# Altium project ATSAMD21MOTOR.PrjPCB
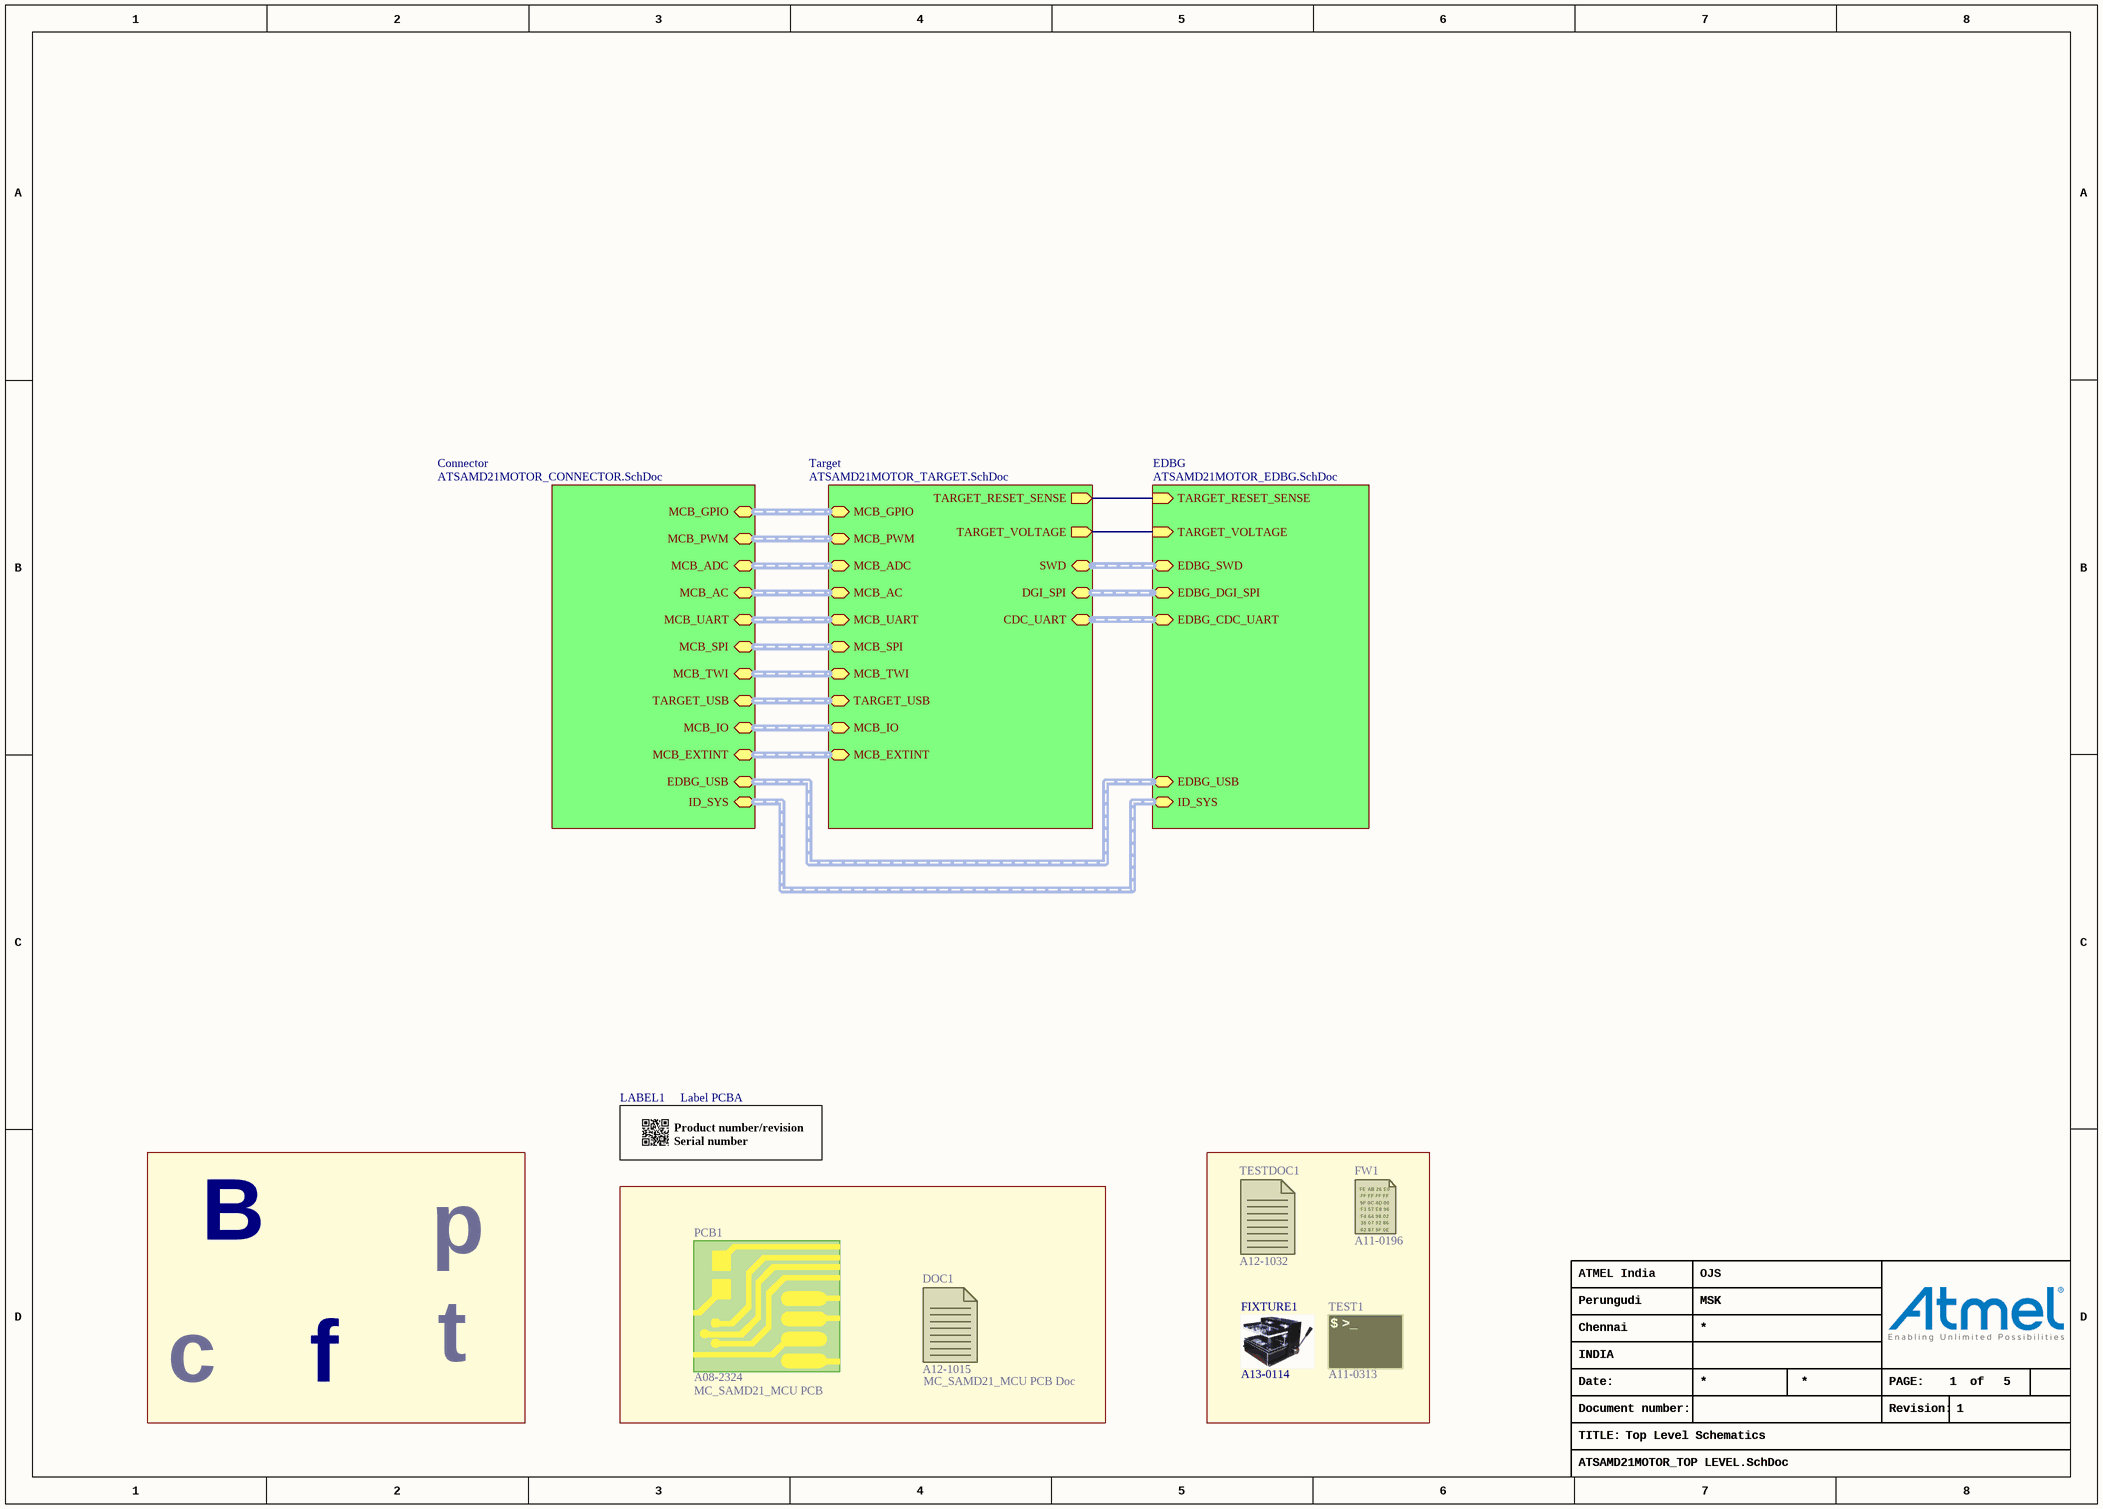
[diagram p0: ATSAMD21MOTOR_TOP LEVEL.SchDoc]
4 sheets, 98 parts. Net scope: hierarchical (ports join the sheet entries above them; power ports are global).
Board file: ATSAMD21MOTOR.PcbDoc
Sheets:
  ATSAMD21MOTOR_TOP LEVEL.SchDoc
    Connector = ATSAMD21MOTOR_CONNECTOR.SchDoc
    EDBG = ATSAMD21MOTOR_EDBG.SchDoc
    Target = ATSAMD21MOTOR_TARGET.SchDoc

## Sheet ATSAMD21MOTOR_TOP LEVEL.SchDoc: Top Level Schematics
size A3; Organization: ATMEL India; Address1: Perungudi; Address2: Chennai; Address3: INDIA; Revision: 1; SheetNumber: 1; SheetTotal: 5; CheckedBy: MSK; DrawnBy: OJS; Engineer: OJS; PageSetup: Record=PageOptions¦CenterHorizontal=True¦CenterVertical=True¦PrintScale=1.01¦XCorrection=1.00¦YCorrection=1.00¦PrintKind=1¦BorderSize=5000000¦LeftOffset=0¦BottomOffset=0¦Orientation=2¦PaperLength=1000¦PaperWidth=1000¦Scale=100¦PaperSource=7¦PrintQuality=-4¦MediaType=1¦DitherType=10¦PaperKind=Letter¦PrintScaleMode=1

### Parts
DOC1  value MC_SAMD21_MCU PCB Doc  AN: A12-1015  (hidden comment: DOCUMENTATION)  (mechanical)
FIXTURE1  AN: A13-0114  (hidden comment: JIG)  (mechanical)
FW1  AN: A11-0196  (hidden comment: FW)  (mechanical)
LABEL1  value Label PCBA  [AP8-00317]  (hidden comment: PCBA_LABEL)
PCB1  value MC_SAMD21_MCU PCB  AN: A08-2324  (hidden comment: PCB)  (mechanical)
TEST1  AN: A11-0313  (hidden comment: TEST)  (mechanical)
TESTDOC1  AN: A12-1032  (hidden comment: TESTDOC)  (mechanical)

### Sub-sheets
Connector = ATSAMD21MOTOR_CONNECTOR.SchDoc: MCB_GPIO (harness MCB_GPIO), MCB_PWM (harness MCB_PWM), MCB_ADC (harness MCB_ADC), MCB_AC (harness MCB_AC), MCB_SPI (harness MCB_SPI), MCB_UART (harness MCB_UART), MCB_TWI (harness MCB_TWI), ID_SYS (harness ID_SYS), EDBG_USB (harness EDBG_USB), TARGET_USB (harness TARGET_USB), MCB_IO (harness MCB_IO), MCB_EXTINT (harness MCB_EXTINT)
EDBG = ATSAMD21MOTOR_EDBG.SchDoc: EDBG_CDC_UART (harness CDC_UART), EDBG_DGI_SPI (harness DGI_SPI), ID_SYS (harness ID_SYS), TARGET_RESET_SENSE (in), EDBG_SWD (harness SWD), EDBG_USB (harness EDBG_USB), TARGET_VOLTAGE (in)
Target = ATSAMD21MOTOR_TARGET.SchDoc: SWD (harness SWD), DGI_SPI (harness DGI_SPI), TARGET_RESET_SENSE (out), MCB_GPIO (harness MCB_GPIO), MCB_PWM (harness MCB_PWM), MCB_ADC (harness MCB_ADC), MCB_AC (harness MCB_AC), MCB_SPI (harness MCB_SPI), MCB_UART (harness MCB_UART), MCB_TWI (harness MCB_TWI), CDC_UART (harness CDC_UART), TARGET_USB (harness TARGET_USB), TARGET_VOLTAGE (out), MCB_IO (harness MCB_IO), MCB_EXTINT (harness MCB_EXTINT)

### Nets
EDBG_ADC0: sheet EDBG/TARGET_VOLTAGE, sheet Target/TARGET_VOLTAGE
TARGET_RESET_SENSE: sheet EDBG/TARGET_RESET_SENSE, sheet Target/TARGET_RESET_SENSE

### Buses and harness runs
harness sheet Connector/EDBG_USB = sheet EDBG/EDBG_USB
harness sheet Connector/ID_SYS = sheet EDBG/ID_SYS
harness sheet Connector/MCB_AC = sheet Target/MCB_AC
harness sheet Connector/MCB_ADC = sheet Target/MCB_ADC
harness sheet Connector/MCB_EXTINT = sheet Target/MCB_EXTINT
harness sheet Connector/MCB_GPIO = sheet Target/MCB_GPIO
harness sheet Connector/MCB_IO = sheet Target/MCB_IO
harness sheet Connector/MCB_PWM = sheet Target/MCB_PWM
harness sheet Connector/MCB_SPI = sheet Target/MCB_SPI
harness sheet Connector/MCB_TWI = sheet Target/MCB_TWI
harness sheet Connector/MCB_UART = sheet Target/MCB_UART
harness sheet Connector/TARGET_USB = sheet Target/TARGET_USB
harness sheet EDBG/EDBG_CDC_UART = sheet Target/CDC_UART
harness sheet EDBG/EDBG_DGI_SPI = sheet Target/DGI_SPI
harness sheet EDBG/EDBG_SWD = sheet Target/SWD

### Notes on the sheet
- B
- p
- c
- f
- t
- Date:
- PAGE:
- of
- TITLE:
- Document number:
- Revision:

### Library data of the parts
DOC1 = A12-1015: MC_SAMD21_MCU PCB Documentation; PartGroup: Documentation,PCBA Documents,Atmel
FIXTURE1 = A13-0114: Test Fixture for BLDC Motor driver; PartGroup: Test Equipment,Test Fixtures
FW1 = A11-0196: EDBG secured firmware; PartGroup: Software,Firmware,Tools
LABEL1 = A09-0611: PCBA identification label PP Top White Gloss; PartGroup: Mechanical devices,Packaging materials,Printed Labels; Manufacturer: ACT Logimark AS; MPN: 505462
PCB1 = A08-2324: MC_SAMD21_MCU PCB gerber; PartGroup: Mechanical devices,Printed circuit boards
TEST1 = A11-0313: ATSAMD21BLDC24V-STK test software; PartGroup: Software,Test software,Starter Kit
TESTDOC1 = A12-1032: ATSAMD21BLDC24V-STK test instruction; PartGroup: Documentation,Procedures,Test Instructions

## Sheet ATSAMD21MOTOR_CONNECTOR.SchDoc: Daughter Board Connector
size A3; Organization: ATMEL India; Address1: Perungudi; Address2: Chennai; Address3: INDIA; Revision: 1; SheetNumber: 3; SheetTotal: 5; CheckedBy: MSK; DrawnBy: OJS; PageSetup: Record=PageOptions¦CenterHorizontal=True¦CenterVertical=True¦PrintScale=1.01¦XCorrection=1.00¦YCorrection=1.00¦PrintKind=1¦BorderSize=5000000¦LeftOffset=0¦BottomOffset=0¦Orientation=2¦PaperLength=1000¦PaperWidth=1000¦Scale=100¦PaperSource=7¦PrintQuality=-4¦MediaType=1¦DitherType=10¦PaperKind=A3 (297 x 420 mm)¦PrintScaleMode=1
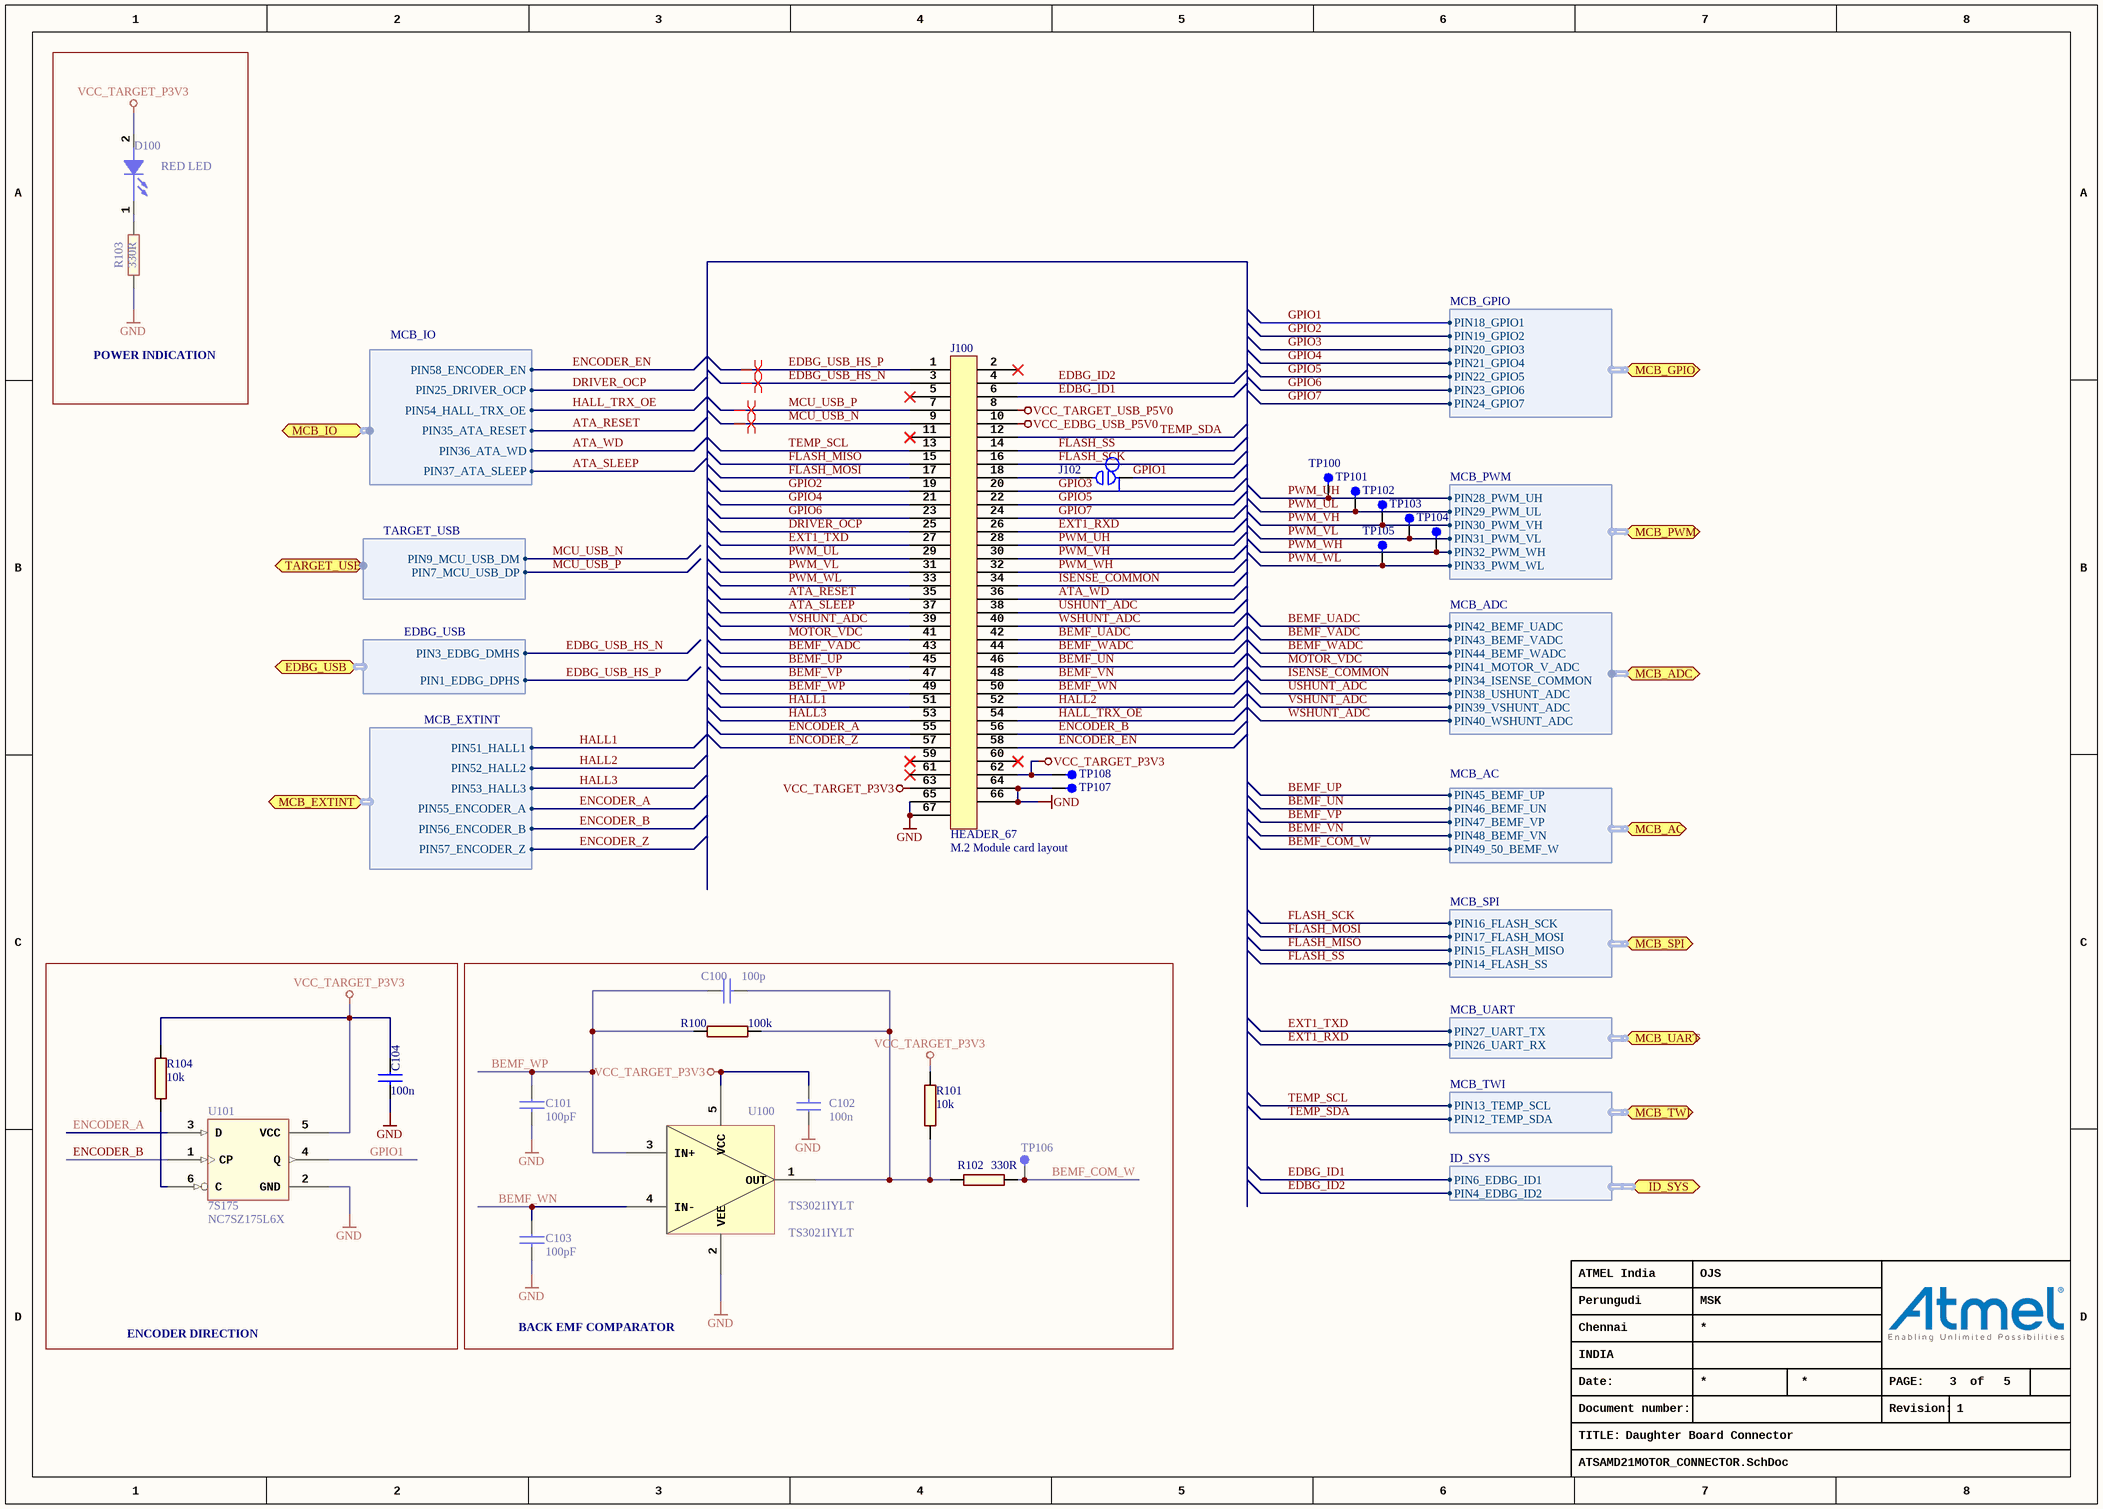
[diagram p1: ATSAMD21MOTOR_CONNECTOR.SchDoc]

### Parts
C100  value 100p  [AP1-00002]  (hidden comment: #Farnell reference  722110RL)
C101  value 100pF  [AP1-00002]  (hidden comment: MPN back-ported from Escatec 29-09-2009)
C102  value 100n  [AP1-00002]  (hidden comment: CAP-NONPOL)
C103  value 100pF  [AP1-00002]  (hidden comment: MPN back-ported from Escatec 29-09-2009)
C104  value 100n  [AP1-00001]  (hidden comment: CAP-NONPOL)
D100  LED_12  [AP4-00013]  (value not drawn)
J100  HEADER_67  value M.2 Module card layout  [AP9-00138]
J102  SMD-STRAP_OPEN  [AP9-00034]  (value not drawn)  (net tie, no BOM)
R100  value 100k  [AP2-00001]  (hidden comment: R2)
R101  value 10k  [AP2-00000]  (hidden comment: R2)
R102  value 330R  [AP2-00001]  (hidden comment: R2)
R103  value 330R  [AP2-00000]  (hidden comment: R2)
R104  value 10k  [AP2-00000]  (hidden comment: R2)
TP100  TESTPOINT  [AP8-00010]  (value not drawn)  (no BOM)
TP101  TESTPOINT  [AP8-00010]  (value not drawn)  (no BOM)
TP102  TESTPOINT  [AP8-00010]  (value not drawn)  (no BOM)
TP103  TESTPOINT  [AP8-00010]  (value not drawn)  (no BOM)
TP104  TESTPOINT  [AP8-00010]  (value not drawn)  (no BOM)
TP105  TESTPOINT  [AP8-00010]  (value not drawn)  (no BOM)
TP106  TESTPOINT  [AP8-00010]  (value not drawn)  (no BOM)
TP107  TESTPOINT  [AP8-00010]  (value not drawn)  (no BOM)
TP108  TESTPOINT  [AP8-00010]  (value not drawn)  (no BOM)
U100  TS3021IYLT  [AP6-00014]
U101  7S175  value NC7SZ175L6X  [AP6-00076]

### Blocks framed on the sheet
ENCODER DIRECTION: C104 R104 U101
BACK EMF COMPARATOR: C100-C103 R100-R102 TP106 U100

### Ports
EDBG_USB (harness EDBG_USB), ID_SYS (harness ID_SYS), MCB_AC (harness MCB_AC), MCB_ADC (harness MCB_ADC), MCB_EXTINT (harness MCB_EXTINT), MCB_GPIO (harness MCB_GPIO), MCB_IO (harness MCB_IO), MCB_PWM (harness MCB_PWM), MCB_SPI (harness MCB_SPI), MCB_TWI (harness MCB_TWI), MCB_UART (harness MCB_UART), TARGET_USB (harness TARGET_USB)

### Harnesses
ID_SYS: PIN4_EDBG_ID2, PIN6_EDBG_ID1
EDBG_USB: PIN3_EDBG_DMHS, PIN1_EDBG_DPHS
MCB_EXTINT: PIN51_HALL1, PIN52_HALL2, PIN53_HALL3, PIN55_ENCODER_A, PIN56_ENCODER_B, PIN57_ENCODER_Z
MCB_GPIO: PIN18_GPIO1, PIN19_GPIO2, PIN20_GPIO3, PIN21_GPIO4, PIN22_GPIO5, PIN23_GPIO6, PIN24_GPIO7
MCB_PWM: PIN28_PWM_UH, PIN29_PWM_UL, PIN30_PWM_VH, PIN31_PWM_VL, PIN32_PWM_WH, PIN33_PWM_WL
MCB_AC: PIN45_BEMF_UP, PIN46_BEMF_UN, PIN47_BEMF_VP, PIN48_BEMF_VN, PIN49_50_BEMF_W
MCB_SPI: PIN16_FLASH_SCK, PIN17_FLASH_MOSI, PIN15_FLASH_MISO, PIN14_FLASH_SS
MCB_UART: PIN26_UART_RX, PIN27_UART_TX
MCB_TWI: PIN13_TEMP_SCL, PIN12_TEMP_SDA
TARGET_USB: PIN9_MCU_USB_DM, PIN7_MCU_USB_DP
MCB_IO: PIN35_ATA_RESET, PIN36_ATA_WD, PIN37_ATA_SLEEP, PIN54_HALL_TRX_OE, PIN25_DRIVER_OCP, PIN58_ENCODER_EN
MCB_ADC: PIN42_BEMF_UADC, PIN43_BEMF_VADC, PIN44_BEMF_WADC, PIN41_MOTOR_V_ADC, PIN34_ISENSE_COMMON, PIN38_USHUNT_ADC, PIN39_VSHUNT_ADC, PIN40_WSHUNT_ADC

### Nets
GND: C101.2 C102.1 C103.2 C104.2 J100.64 J100.65 J100.66 J100.67 R103.1 TP107.1 U100.2(VEE) U101.2(GND)
VCC_EDBG_USB_P5V0: J100.10
VCC_TARGET_P3V3: C102.2 C104.1 D100.2(ANODE) J100.62 J100.63 R101.2 R104.2 TP108.1 U100.5(VCC) U101.5(VCC)
VCC_TARGET_USB_P5V0: J100.8
ATA_RESET: J100.35 ; port MCB_IO.PIN35_ATA_RESET
ATA_SLEEP: J100.37 ; port MCB_IO.PIN37_ATA_SLEEP
ATA_WD: J100.36 ; port MCB_IO.PIN36_ATA_WD
BEMF_COM_W: R102.2 TP106.1 ; port MCB_AC.PIN49_50_BEMF_W
BEMF_UADC: J100.42 ; port MCB_ADC.PIN42_BEMF_UADC
BEMF_UN: J100.46 ; port MCB_AC.PIN46_BEMF_UN
BEMF_UP: J100.45 ; port MCB_AC.PIN45_BEMF_UP
BEMF_VADC: J100.43 ; port MCB_ADC.PIN43_BEMF_VADC
BEMF_VN: J100.48 ; port MCB_AC.PIN48_BEMF_VN
BEMF_VP: J100.47 ; port MCB_AC.PIN47_BEMF_VP
BEMF_WADC: J100.44 ; port MCB_ADC.PIN44_BEMF_WADC
BEMF_WN: C103.1 J100.50 U100.4(IN-)
BEMF_WP: C100.1 C101.1 J100.49 R100.1 U100.3(IN+)
DRIVER_OCP: J100.25 ; port MCB_IO.PIN25_DRIVER_OCP
EDBG_ID1: J100.6 ; port ID_SYS.PIN6_EDBG_ID1
EDBG_ID2: J100.4 ; port ID_SYS.PIN4_EDBG_ID2
EDBG_USB_HS_N: J100.3 ; port EDBG_USB.PIN3_EDBG_DMHS
EDBG_USB_HS_P: J100.1 ; port EDBG_USB.PIN1_EDBG_DPHS
ENCODER_A: J100.55 U101.3(D) ; port MCB_EXTINT.PIN55_ENCODER_A
ENCODER_B: J100.56 U101.1(CP) ; port MCB_EXTINT.PIN56_ENCODER_B
ENCODER_EN: J100.58 ; port MCB_IO.PIN58_ENCODER_EN
ENCODER_Z: J100.57 ; port MCB_EXTINT.PIN57_ENCODER_Z
EXT1_RXD: J100.26 ; port MCB_UART.PIN26_UART_RX
EXT1_TXD: J100.27 ; port MCB_UART.PIN27_UART_TX
FLASH_MISO: J100.15 ; port MCB_SPI.PIN15_FLASH_MISO
FLASH_MOSI: J100.17 ; port MCB_SPI.PIN17_FLASH_MOSI
FLASH_SCK: J100.16 ; port MCB_SPI.PIN16_FLASH_SCK
FLASH_SS: J100.14 ; port MCB_SPI.PIN14_FLASH_SS
GPIO1: J102.1 U101.4(Q) ; port MCB_GPIO.PIN18_GPIO1
GPIO2: J100.19 ; port MCB_GPIO.PIN19_GPIO2
GPIO3: J100.20 ; port MCB_GPIO.PIN20_GPIO3
GPIO4: J100.21 ; port MCB_GPIO.PIN21_GPIO4
GPIO5: J100.22 ; port MCB_GPIO.PIN22_GPIO5
GPIO6: J100.23 ; port MCB_GPIO.PIN23_GPIO6
GPIO7: J100.24 ; port MCB_GPIO.PIN24_GPIO7
HALL1: J100.51 ; port MCB_EXTINT.PIN51_HALL1
HALL2: J100.52 ; port MCB_EXTINT.PIN52_HALL2
HALL3: J100.53 ; port MCB_EXTINT.PIN53_HALL3
HALL_TRX_OE: J100.54 ; port MCB_IO.PIN54_HALL_TRX_OE
ISENSE_COMMON: J100.34 ; port MCB_ADC.PIN34_ISENSE_COMMON
MCU_USB_N: J100.9 ; port TARGET_USB.PIN9_MCU_USB_DM
MCU_USB_P: J100.7 ; port TARGET_USB.PIN7_MCU_USB_DP
MOTOR_VDC: J100.41 ; port MCB_ADC.PIN41_MOTOR_V_ADC
PWM_UH: J100.28 TP100.1 ; port MCB_PWM.PIN28_PWM_UH  [project net PA08_TCC0_WO0]
PWM_UL: J100.29 TP101.1 ; port MCB_PWM.PIN29_PWM_UL  [project net PA14_TCC0_WO4]
PWM_VH: J100.30 TP102.1 ; port MCB_PWM.PIN30_PWM_VH  [project net PA09_TCC0_WO1]
PWM_VL: J100.31 TP103.1 ; port MCB_PWM.PIN31_PWM_VL  [project net PA15_TCC0_WO5]
PWM_WH: J100.32 TP104.1 ; port MCB_PWM.PIN32_PWM_WH  [project net PA10_TCC0_WO2]
PWM_WL: J100.33 TP105.1 ; port MCB_PWM.PIN33_PWM_WL  [project net PA16_TCC0_WO6]
TEMP_SCL: J100.13 ; port MCB_TWI.PIN13_TEMP_SCL  [project net PA23_S3_PAD1]
TEMP_SDA: J100.12 ; port MCB_TWI.PIN12_TEMP_SDA  [project net PA22_S3_PAD0]
USHUNT_ADC: J100.38 ; port MCB_ADC.PIN38_USHUNT_ADC  [project net PB04_ADC_AIN12]
VSHUNT_ADC: J100.39 ; port MCB_ADC.PIN39_VSHUNT_ADC  [project net PB05_ADC_AIN13]
WSHUNT_ADC: J100.40 ; port MCB_ADC.PIN40_WSHUNT_ADC  [project net PA11_ADC_AIN19]
NetC100_2: C100.2 R100.2 R101.1 R102.1 U100.1(OUT)
NetD100_1: D100.1(CATHODE) R103.2
NetJ100_18: J100.18 J102.2
NetR104_1: R104.1 U101.6(C)

Not connected (* = marked no-connect by the designer): J100 2* 5* 11* 59* 60* 61*

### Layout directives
differential pair: EDBG_USB_HS_N, EDBG_USB_HS_P, MCU_USB_N, MCU_USB_P

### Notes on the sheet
- (near D100) RED LED
- POWER INDICATION

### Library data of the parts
C100 = A01-0435: Ceramic Cap, 100pF, 50V, +/-10%, 0603, X7R; PartGroup: Capacitors,Ceramic,SMD 0603; Manufacturer: PHYCOMP; MPN: CC0603KRX7R9BB101; Tolerance: 100V +/-1%; TemperatureRange: -55C to 125C
C101 C103 = A01-0101: Ceramic capacitor, SMD 0603, X7R, 50V, ±10 %; PartGroup: Capacitors,Ceramic,SMD 0603; Manufacturer: AVX; MPN: 06035C102KAT2A; TemperatureRange: -55 - +125 deg C
C102 = A01-0087: Ceramic capacitor, SMD 0603, X7R, 16V, +/-10 %; PartGroup: Capacitors,Ceramic,SMD 0603; Manufacturer: AVX; MPN: 0603YC104KAT2A; TemperatureRange: -55 - +125 deg C
C104 = A01-0246: Ceramic capacitor, SMD 0402, X7R, 16V, +/-10%; PartGroup: Capacitors,Ceramic,SMD 0402; Manufacturer: Kemet; MPN: C0402C104K4RACTU; TemperatureRange: -55 - +125 deg C
D100 = A10-0017: LED, Red, Wave length=639nm, SMD 0805, Â±70Â°; PartGroup: Opto,LEDs,SMD; Manufacturer: Everlight; Value: EL17-21SURC; TemperatureRange: -40 to +85 deg C
J100 = A08-2293: 2199230-3 M.2 NGFF Module card layout; PartGroup: Mechanical devices,Other
J102 = A09-0483: Default open SMD strap; PartGroup: Mechanical devices,PCB implemented components
R100 = A02-0122: Thick film resistor, SMD 0603, 1/10W, 1%; PartGroup: Resistors,SMD,0603 1%; Manufacturer: Panasonic; MPN: ERJ-3EKF1003V
R101 R104 = A02-0236: Thick film resistor, SMD 0402, 1/16W, 1%; PartGroup: Resistors,SMD,0402 1%; Manufacturer: vishay; MPN: CRCW040210K0FKED; TemperatureRange: -55 - +125 deg C
R102 = A02-0062: Thick film resistor, SMD 0603, 1/10W, 1%; PartGroup: Resistors,SMD,0603 1%
R103 = A02-0200: Thick film resistor, SMD 0402, 1/16W, 1%; PartGroup: Resistors,SMD,0402 1%; TemperatureRange: -55 - +125 deg C
TP100-TP108 = A08-0004: Single SMD testpad; PartGroup: Mechanical devices,Connectors,Test points
U100 = A06-1251: Analog Comparators RR 1.8V Comparator 38ns 73uA 1.8 to 5V; PartGroup: Integrated Circuits,General linear,Comparator; Manufacturer: ST; TemperatureRange: -40Â°C +125Â°C
U101 = A06-0015: TinyLogic D-Type Flip-Flop with asynchronous Clear; PartGroup: Integrated Circuits,Discrete logic,SMD single gate; Manufacturer: Fairchild; TemperatureRange: -40 - +85 deg C

## Sheet ATSAMD21MOTOR_EDBG.SchDoc: Embedded Debugger (EDBG)
size A3; Organization: ATMEL India; Address1: Perungudi; Address2: Chennai; Address3: INDIA; Revision: 1; SheetNumber: 5; SheetTotal: 5; CheckedBy: MSK; DrawnBy: OJS; PageSetup: Record=PageOptions¦CenterHorizontal=True¦CenterVertical=True¦PrintScale=0.73¦XCorrection=1.00¦YCorrection=1.00¦PrintKind=1¦BorderSize=5000000¦LeftOffset=0¦BottomOffset=0¦Orientation=2¦PaperLength=1000¦PaperWidth=1000¦Scale=100¦PaperSource=7¦PrintQuality=-4¦MediaType=1¦DitherType=10¦PaperKind=A3 (297 x 420 mm)¦PrintScaleMode=1
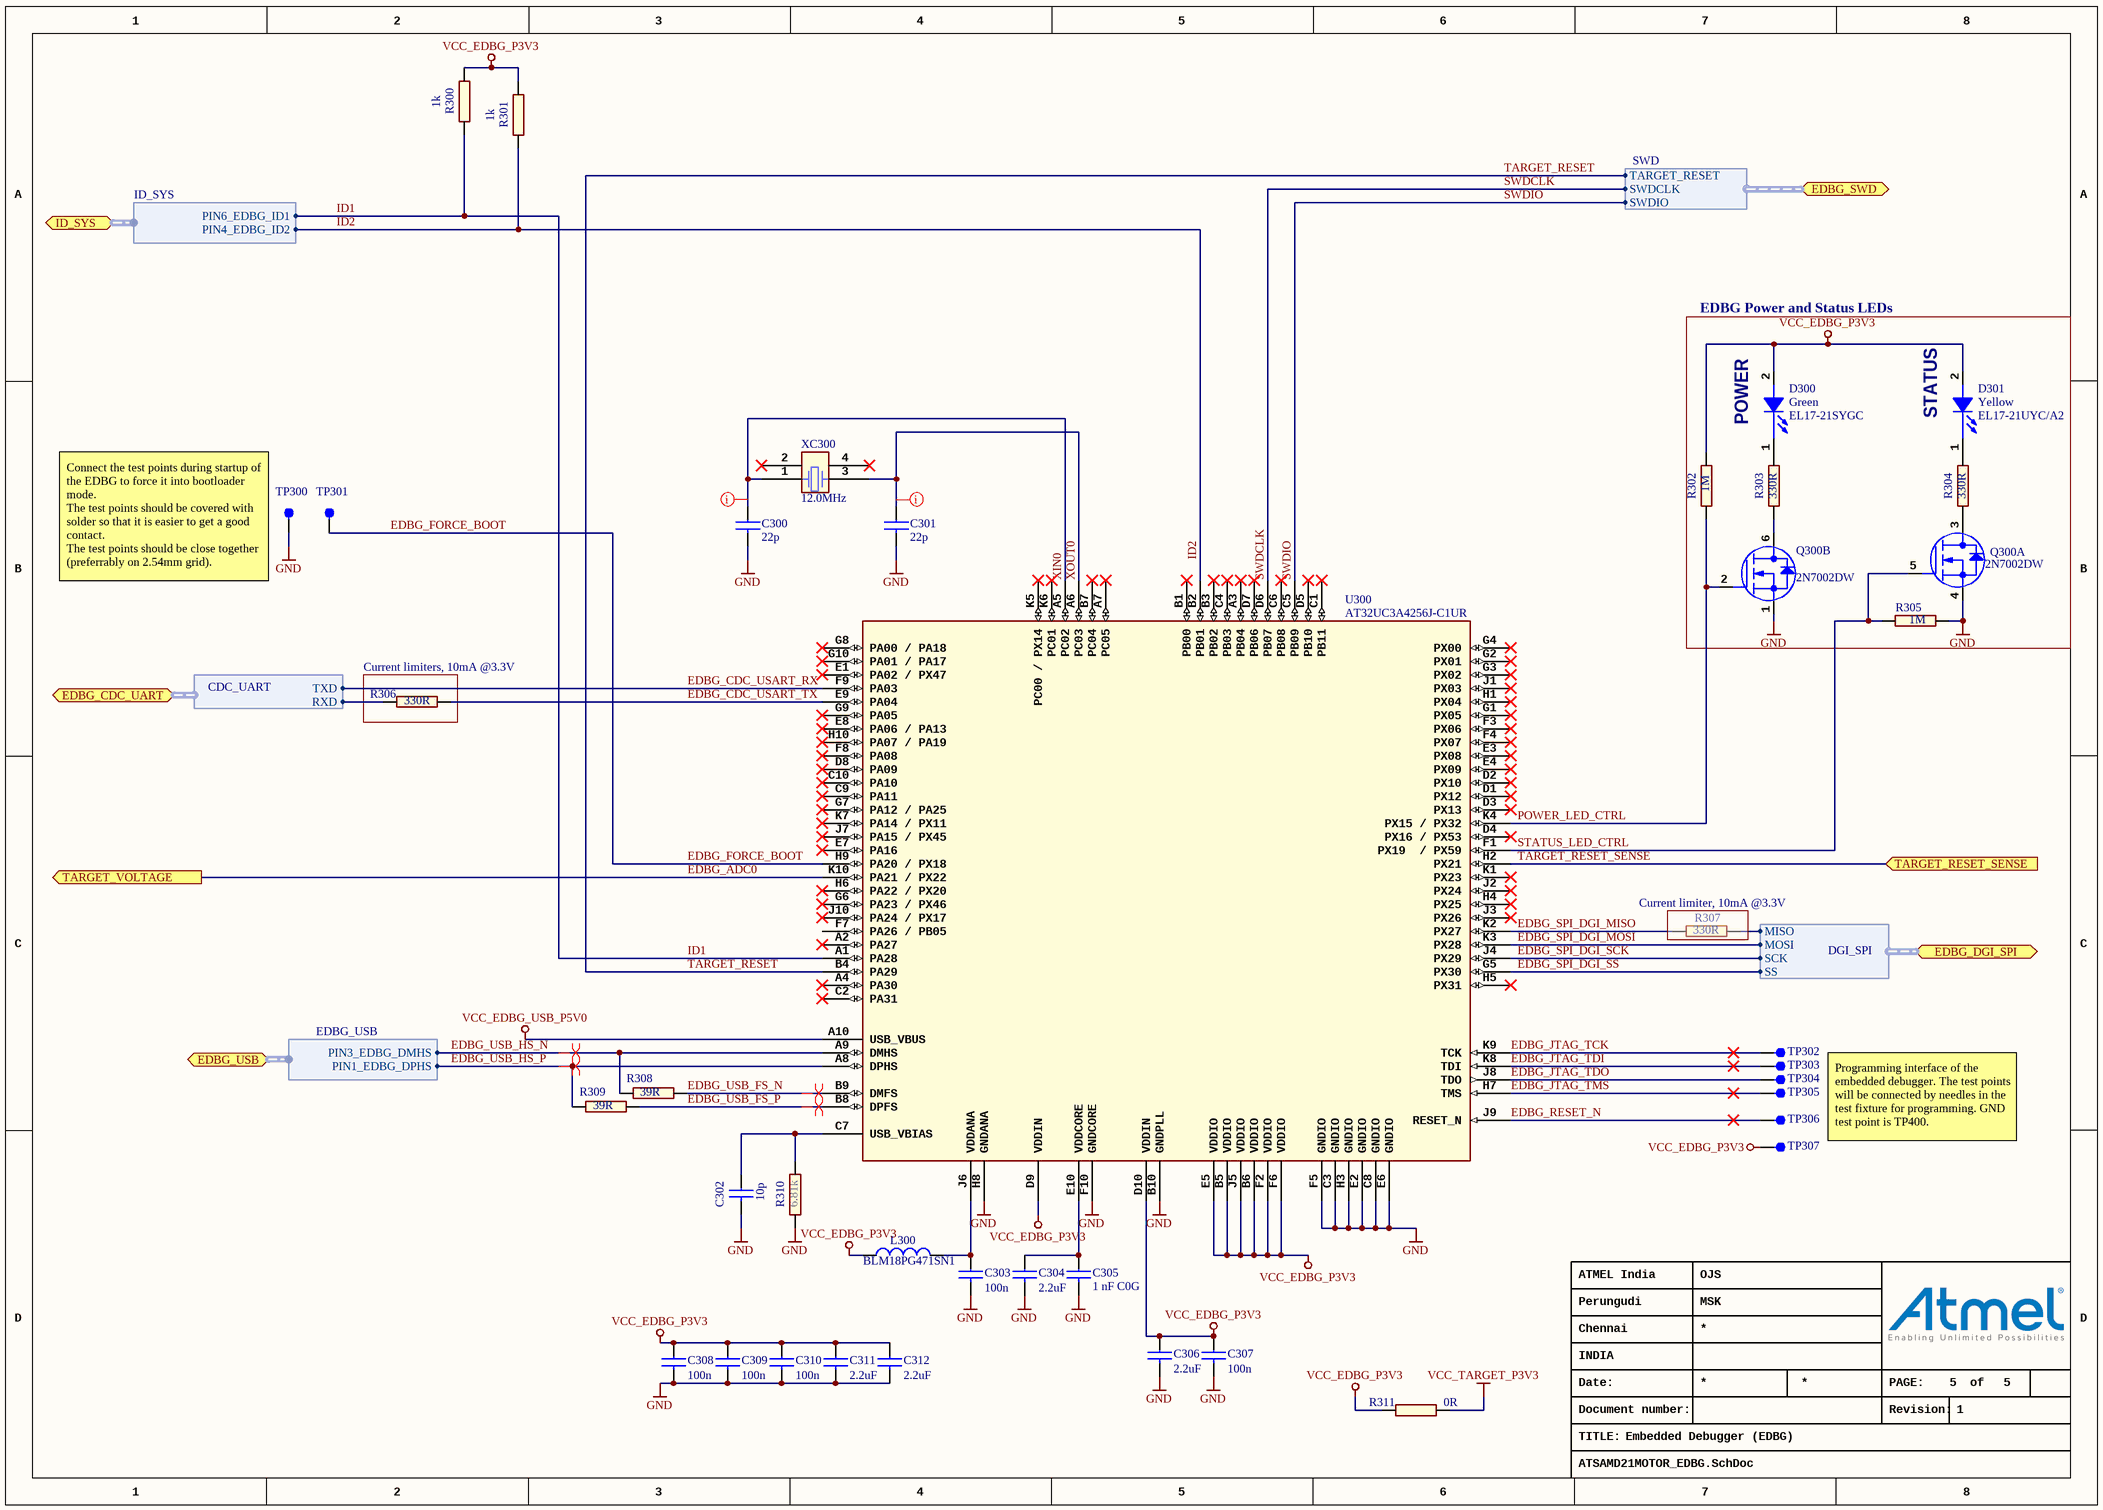
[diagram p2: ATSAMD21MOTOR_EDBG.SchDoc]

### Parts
C300  22p  [AP1-00053]
C301  22p  [AP1-00053]
C302  10p  [AP1-00053]
C303  100n  [AP1-00053]
C304  value 2.2uF  [AP1-00053]  (hidden comment: Farnell no: 1288200)
C305  1 nF C0G  [AP1-00053]
C306  value 2.2uF  [AP1-00053]  (hidden comment: Farnell no: 1288200)
C307  100n  [AP1-00053]
C308  100n  [AP1-00053]
C309  100n  [AP1-00053]
C310  100n  [AP1-00053]
C311  value 2.2uF  [AP1-00053]  (hidden comment: Farnell no: 1288200)
C312  value 2.2uF  [AP1-00053]  (hidden comment: Farnell no: 1288200)
D300  Green  value EL17-21SYGC  [AP4-00013]
D301  Yellow  value EL17-21UYC/A2  [AP4-00013]
L300  BLM18PG471SN1  [AP3-00005]
Q300  value 2N7002DW  [AP5-00001]  (hidden comment: Same as 2N7002 but with two MOSFETs in one package)  (parts A,B of 2)
R300  value 1k  [AP2-00000]  (hidden comment: R2)
R301  value 1k  [AP2-00000]  (hidden comment: R2)
R302  value 1M  [AP2-00000]  (hidden comment: R2)
R303  value 330R  [AP2-00000]  (hidden comment: R2)
R304  value 330R  [AP2-00000]  (hidden comment: R2)
R305  value 1M  [AP2-00000]  (hidden comment: R2)
R306  value 330R  [AP2-00000]  (hidden comment: R2)
R307  value 330R  [AP2-00000]  (hidden comment: R2)
R308  value 39R  [AP2-00011]  (hidden comment: R2)
R309  value 39R  [AP2-00011]  (hidden comment: R2)
R310  value 6.81k  [AP2-00011]  (hidden comment: R2)
R311  value 0R  [AP2-00001]  (hidden comment: R2)
TP300  TESTPAD  [AP8-00010]  (value not drawn)  (no BOM)
TP301  TESTPAD  [AP8-00010]  (value not drawn)  (no BOM)
TP302  TESTPAD  [AP8-00010]  (value not drawn)  (no BOM)
TP303  TESTPAD  [AP8-00010]  (value not drawn)  (no BOM)
TP304  TESTPAD  [AP8-00010]  (value not drawn)  (no BOM)
TP305  TESTPAD  [AP8-00010]  (value not drawn)  (no BOM)
TP306  TESTPAD  [AP8-00010]  (value not drawn)  (no BOM)
TP307  TESTPAD  [AP8-00010]  (value not drawn)  (no BOM)
U300  value AT32UC3A4256J-C1UR  [AP6-00206]  (hidden comment: 100 ball VFBGA)
XC300  12.0MHz  [AP7-00039]

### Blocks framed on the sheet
Current limiters, 10mA @3.3V: R306

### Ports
EDBG_CDC_UART (harness CDC_UART), EDBG_DGI_SPI (harness DGI_SPI), EDBG_SWD (harness SWD), EDBG_USB (harness EDBG_USB), ID_SYS (harness ID_SYS), TARGET_RESET_SENSE (in), TARGET_VOLTAGE (out)

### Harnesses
CDC_UART: TXD, RXD
DGI_SPI: MISO, MOSI, SCK, SS
SWD: SWDCLK, SWDIO, TARGET_RESET
ID_SYS: PIN4_EDBG_ID2, PIN6_EDBG_ID1
EDBG_USB: PIN3_EDBG_DMHS, PIN1_EDBG_DPHS

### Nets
GND: C300.2 C301.2 C302.2 C303.2 C304.2 C305.2 C306.2 C307.2 C308.2 C309.2 C310.2 C311.2 C312.2 Q300.1(S2) Q300.4(S1) R305.1 R310.1 TP300.1 U300.B10(GNDPLL) U300.C3(GNDIO) U300.C8(GNDIO) U300.E2(GNDIO) U300.E6(GNDIO) U300.F5(GNDIO) U300.F10(GNDCORE) U300.H3(GNDIO) U300.H8(GNDANA)
VCC_EDBG_P3V3: C306.1 C307.1 C308.1 C309.1 C310.1 C311.1 C312.1 D300.2(ANODE) D301.2(ANODE) L300.1 R300.2 R301.2 R302.2 R311.1 TP307.1 U300.B5(VDDIO) U300.B6(VDDIO) U300.D9(VDDIN) U300.D10(VDDIN) U300.E5(VDDIO) U300.F2(VDDIO) U300.F6(VDDIO) U300.J5(VDDIO)
VCC_EDBG_USB_P5V0: U300.A10(USB_VBUS)
VCC_TARGET_P3V3: R311.2
EDBG_ADC0: U300.K10(PA21_/_PX22) ; port TARGET_VOLTAGE
EDBG_CDC_USART_RX: U300.F9(PA03) ; port EDBG_CDC_UART.TXD
EDBG_CDC_USART_TX: R306.2 U300.E9(PA04)
EDBG_FORCE_BOOT: TP301.1 U300.H9(PA20_/_PX18)
EDBG_JTAG_TCK: TP302.1 U300.K9(TCK)
EDBG_JTAG_TDI: TP303.1 U300.K8(TDI)
EDBG_JTAG_TDO: TP304.1 U300.J8(TDO)
EDBG_JTAG_TMS: TP305.1 U300.H7(TMS)
EDBG_RESET_N: TP306.1 U300.J9(RESET_N)
EDBG_SPI_DGI_MISO: R307.1 U300.K2(PX27)
EDBG_SPI_DGI_MOSI: U300.K3(PX28) ; port EDBG_DGI_SPI.MOSI
EDBG_SPI_DGI_SCK: U300.J4(PX29) ; port EDBG_DGI_SPI.SCK
EDBG_SPI_DGI_SS: U300.G5(PX30) ; port EDBG_DGI_SPI.SS
EDBG_USB_FS_N: R308.2 U300.B9(DMFS)
EDBG_USB_FS_P: R309.2 U300.B8(DPFS)
EDBG_USB_HS_N: R308.1 U300.A9(DMHS) ; port EDBG_USB.PIN3_EDBG_DMHS
EDBG_USB_HS_P: R309.1 U300.A8(DPHS) ; port EDBG_USB.PIN1_EDBG_DPHS
ID1: R300.1 U300.A1(PA28) ; port ID_SYS.PIN6_EDBG_ID1  [project net EDBG_ID1]
ID2: R301.1 U300.B2(PB01) ; port ID_SYS.PIN4_EDBG_ID2  [project net EDBG_ID2]
PB12_S4_PAD0: R307.2 ; port EDBG_DGI_SPI.MISO
POWER_LED_CTRL: Q300.2(G2) R302.1 U300.K4(PX15_/_PX32)
STATUS_LED_CTRL: Q300.5(G1) R305.2 U300.F1(PX19__/_PX59)
SWDCLK: U300.D6(PB07) ; port EDBG_SWD.SWDCLK  [project net PA30_SWDCLK]
SWDIO: U300.C5(PB09) ; port EDBG_SWD.SWDIO  [project net PA31_SWDIO]
TARGET_RESET: U300.B4(PA29) ; port EDBG_SWD.TARGET_RESET
TARGET_RESET_SENSE: U300.H2(PX21) ; port TARGET_RESET_SENSE
XIN0: C300.1 U300.A5(PC02) XC300.1
XOUT0: C301.1 U300.A6(PC03) XC300.3
NetC302_1: C302.1 R310.2 U300.C7(USB_VBIAS)
NetC303_1: C303.1 L300.2 U300.J6(VDDANA)
NetC304_1: C304.1 C305.1 U300.E10(VDDCORE)
NetD300_1: D300.1(CATHODE) R303.2
NetD301_1: D301.1(CATHODE) R304.2
NetJ201_2: R306.1 ; port EDBG_CDC_UART.RXD
NetQ300_3: Q300.3(D1) R304.1
NetQ300_6: Q300.6(D2) R303.1

Not connected (* = marked no-connect by the designer): U300 A2(PA27)* A3(PB04)* A4(PA30)* A7(PC05)* B1(PB00)* B3(PB02)* B7(PC04)* C1(PB11)* C2(PA31)* C4(PB03)* C6(PB08)* C9(PA11)* C10(PA10)* D1(PX12)* D2(PX10)* D3(PX13)* D4(PX16_/_PX53)* D5(PB10)* D7(PB06)* D8(PA09)* E1(PA02_/_PX47)* E3(PX08)* E4(PX09)* E7(PA16)* E8(PA06_/_PA13)* F3(PX06)* F4(PX07)* F7(PA26_/_PB05) F8(PA08)* G1(PX05)* G2(PX01)* G3(PX02)* G4(PX00)* G6(PA23_/_PX46)* G7(PA12_/_PA25)* G8(PA00_/_PA18)* G9(PA05)* G10(PA01_/_PA17)* H1(PX04)* H4(PX25)* H5(PX31)* H6(PA22_/_PX20)* H10(PA07_/_PA19)* J1(PX03)* J2(PX24)* J3(PX26)* J7(PA15_/_PX45)* J10(PA24_/_PX17)* K1(PX23)* K5(PC00_/_PX14)* K6(PC01)* K7(PA14_/_PX11)*; XC300 2* 4*

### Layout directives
differential pair; rule Assembly Testpoint Usage [Testpoint - Not Allowed    Multiple - Not Allowed]: EDBG_USB_FS_N, EDBG_USB_FS_P, EDBG_USB_HS_N, EDBG_USB_HS_P
rule Assembly Testpoint Usage [Testpoint - Not Allowed    Multiple - Not Allowed]: XIN0, XOUT0

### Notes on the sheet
- EDBG Power and Status LEDs
- (near D300) POWER
- (near D301) STATUS
- (near TP300) Connect the test points during startup of the EDBG to force it into bootloader mode.
  The test points should be covered with solder so that it is easier to get a good contact.
  The test points should be close together (preferrably on 2.54mm grid).
- (near R307) Current limiter, 10mA @3.3V
- Programming interface of the embedded debugger. The test points will be connected by needles in the test fixture for programming. GND test point is TP400.

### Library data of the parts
C300 C301 = A01-0019: Ceramic capacitor, SMD 0402, NP0, 50V, +/-5%; PartGroup: Capacitors,Ceramic,SMD 0402; TemperatureRange: -55 - +125 deg C
C302 = A01-0015: Ceramic capacitor, SMD 0402, NP0, 50V, +/-5%; PartGroup: Capacitors,Ceramic,SMD 0402; TemperatureRange: -55 - +125 deg C
C303 C307-C310 = A01-0246: as C104 on sheet ATSAMD21MOTOR_CONNECTOR
C304 C306 C311 C312 = A01-0300: Ceramic capacitor, SMD 0402, X5R, 6.3V, +/-20%; PartGroup: Capacitors,Ceramic,SMD 0402; Manufacturer: Kemet; MPN: C0402C225M9PAC; Tolerance: ±20%; TemperatureRange: -55°C to +85°C
C305 = A01-0321: Ceramic capacitor, SMD 0402, C0G, 50V, +/-5%; PartGroup: Capacitors,Ceramic,SMD 0402; Manufacturer: Murata; MPN: GRM1555C1H102JA01D; Tolerance: 5%
D300 = A10-0018: LED, Green, Wave length=575nm, SMD 0805, ±70°; PartGroup: Opto,LEDs,SMD; Manufacturer: Everlight; TemperatureRange: -40 - +85 deg C
D301 = A10-0019: LED, Yellow, Wave length=591nm, SMD 0805, ±70°; PartGroup: Opto,LEDs,SMD; Manufacturer: Everlight; MPN: 17-21UYC/S530-A3/TR8; TemperatureRange: -40 to +85 deg C
L300 = A03-0035: SMD RF inductor 0603. Z=470Ohm (@100MHz), Max R(dc)=0.65Ohm, Max current=1A; PartGroup: Inductors,EMI; Manufacturer: Murata; Tolerance: ±25%; TemperatureRange: -55°C to +125°C
Q300 = A05-0051: Dual N-Channel MOSFET, 60V, 115mA cont,RDS(ON) < 7.5 Ohm @50mA@5V, SOT-363; PartGroup: Transistors,Small signal FET,SMD; Manufacturer: Fairchild; TemperatureRange: -65 to 150 deg C
R300 R301 = A02-0212: Thick film resistor, SMD 0402, 1/16W, 1%; PartGroup: Resistors,SMD,0402 1%; TemperatureRange: -55 - +125 deg C
R302 R305 = A02-0284: Thick film resistor, SMD 0402, 1/16W, 1%; PartGroup: Resistors,SMD,0402 1%; Manufacturer: KOA; MPN: RK73H1ETTP1004F; TemperatureRange: -55 - +125 deg C
R303 R304 R306 R307 = A02-0200: as R103 on sheet ATSAMD21MOTOR_CONNECTOR
R308 R309 = A02-0178: Thick film resistor, SMD 0402, 1/16W, 1%; PartGroup: Resistors,SMD,0402 1%; TemperatureRange: -55 - +125 deg C
R310 = A02-0539: Thick film resistor, SMD 0402, 1/16W, 1%; PartGroup: Resistors,SMD,0402 1%; TemperatureRange: -55 - +125 deg C
R311 = A02-0001: Thick film resistor, SMD 0603, 1/10W, 1%; PartGroup: Resistors,SMD,0603 1%; Manufacturer: Panasonic; MPN: ERJ-3GEY0R00V
TP300-TP307 = A08-0004: as TP100 on sheet ATSAMD21MOTOR_CONNECTOR
U300 = A06-0736: AVR 32-bit RISC MCU; PartGroup: Integrated Circuits,MCU, MPU, DSP,AVR MCU; Manufacturer: ATMEL; TemperatureRange: -40 to +85 deg C
XC300 = A07-0042: Fox FQ5032B 12.0MHz SMD crystal 738B-12; PartGroup: Frequency devices,Crystals,SMD; Manufacturer: Fox  Electronics; MPN: FQ5032B-12-C-C-C-200-1; Tolerance: 30PPM

## Sheet ATSAMD21MOTOR_TARGET.SchDoc: Target MCU
size A3; Organization: ATMEL India; Address1: Perungudi; Address2: Chennai; Address3: INDIA; Revision: 1; SheetNumber: 4; SheetTotal: 5; CheckedBy: MSK; DrawnBy: OJS; PageSetup: Record=PageOptions¦CenterHorizontal=True¦CenterVertical=True¦PrintScale=1.01¦XCorrection=1.00¦YCorrection=1.00¦PrintKind=1¦BorderSize=5000000¦LeftOffset=0¦BottomOffset=0¦Orientation=2¦PaperLength=1000¦PaperWidth=1000¦Scale=100¦PaperSource=7¦PrintQuality=-4¦MediaType=1¦DitherType=10¦PaperKind=A3 (297 x 420 mm)¦PrintScaleMode=1
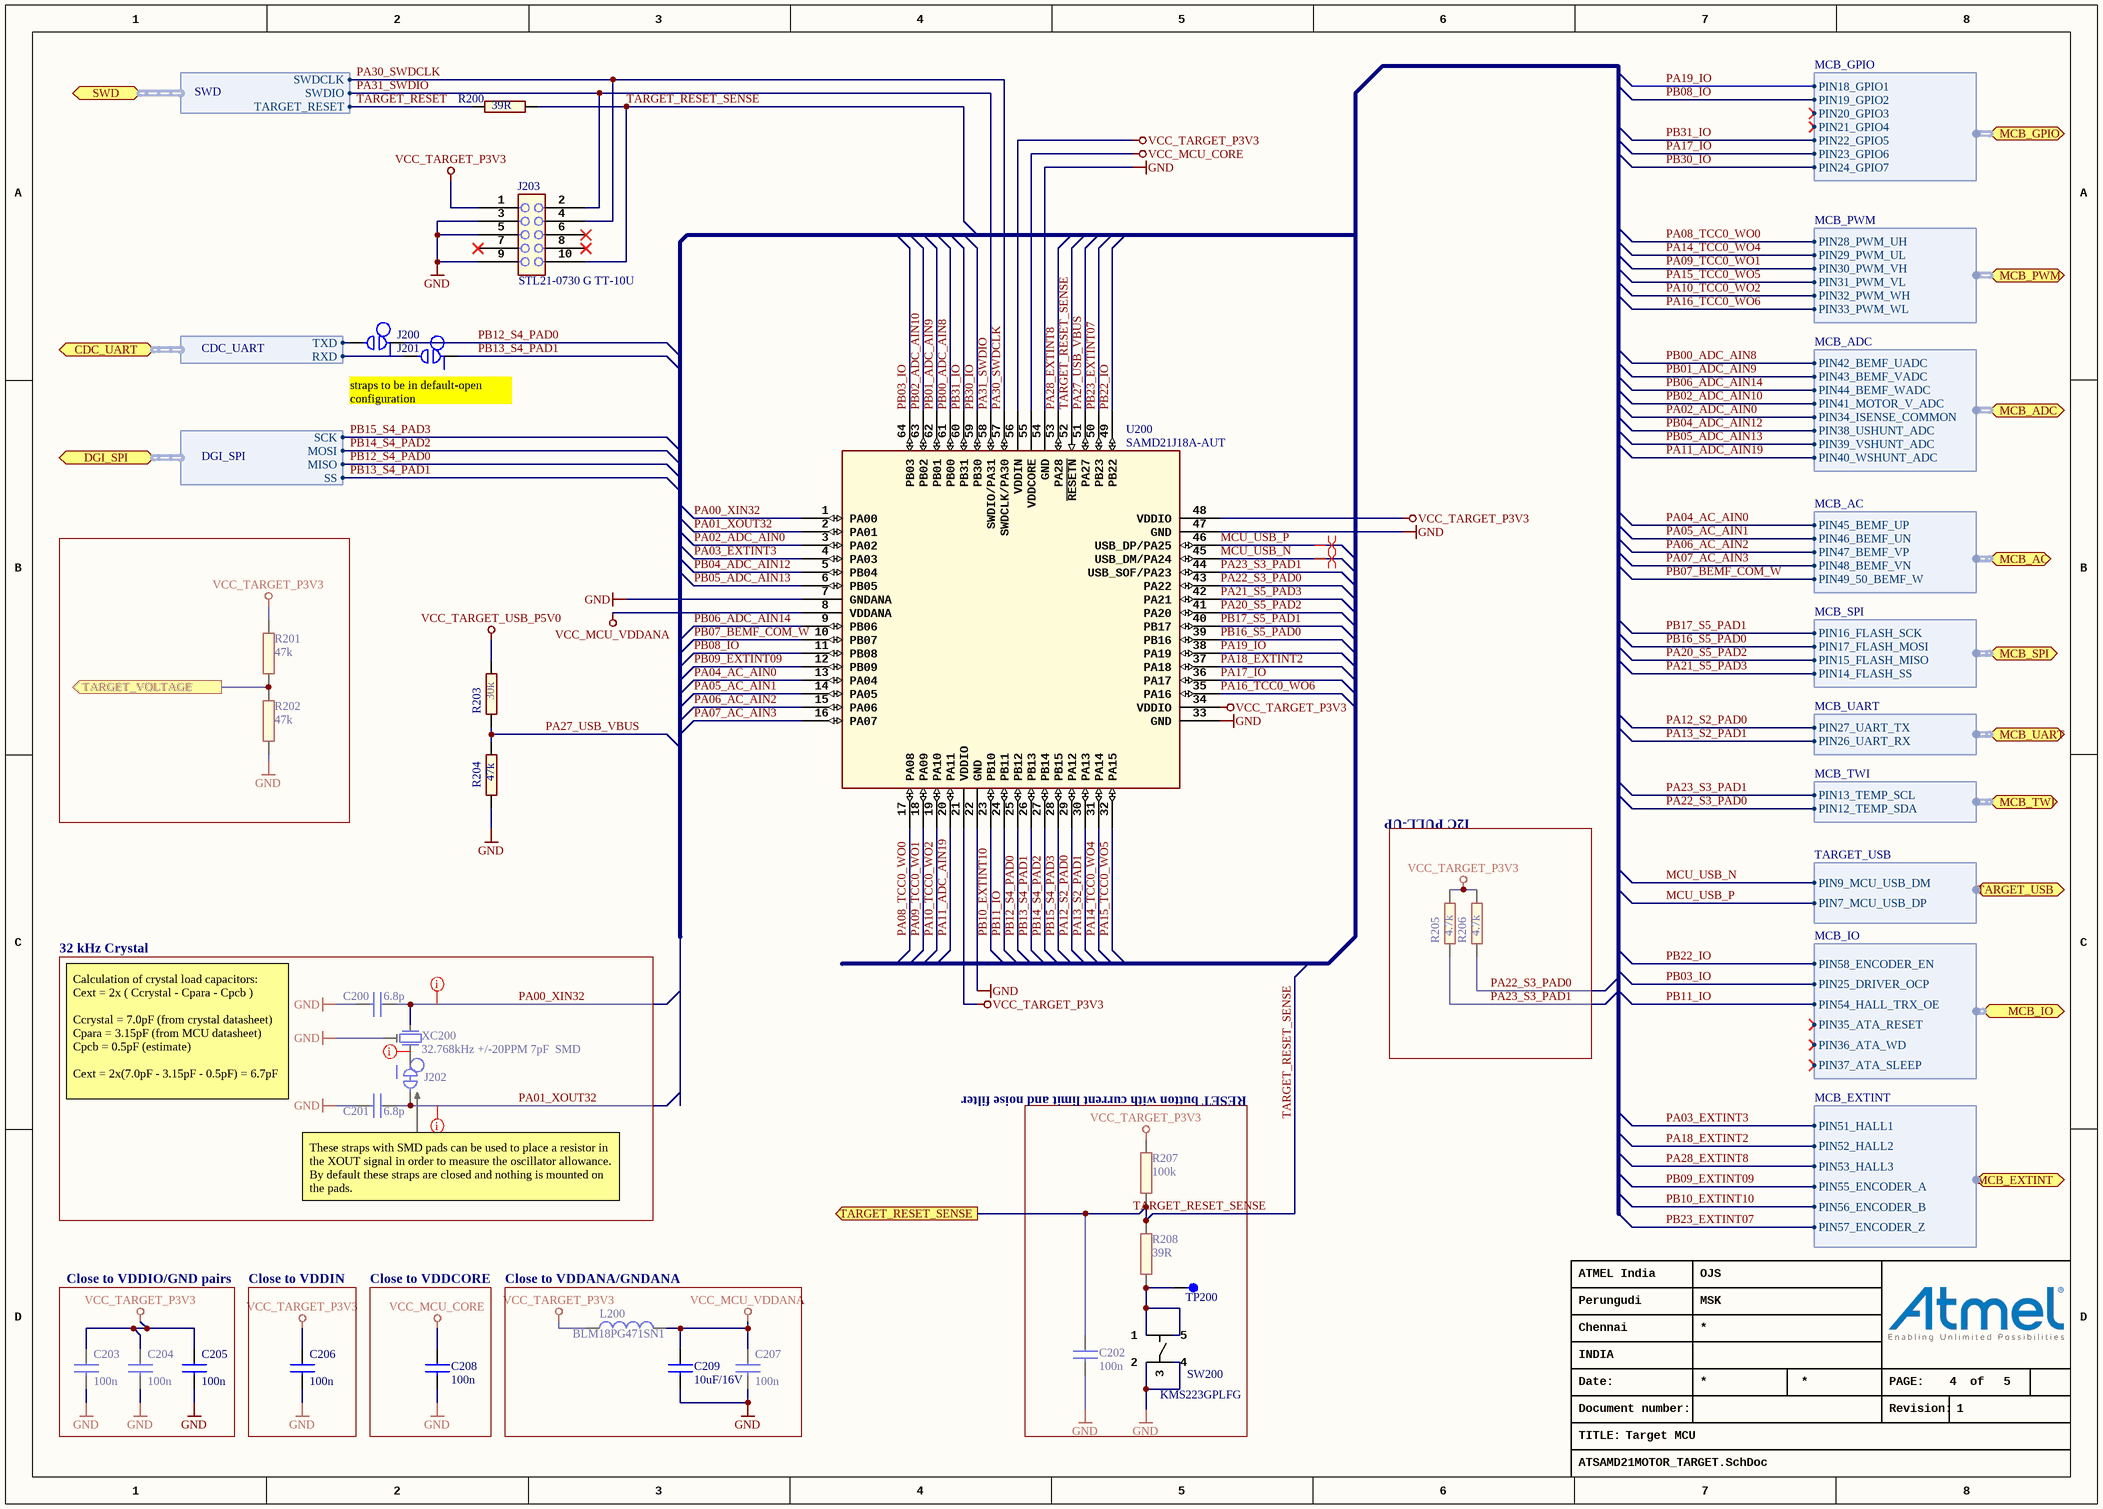
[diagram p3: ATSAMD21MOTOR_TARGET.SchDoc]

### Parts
C200  value 6.8p  [AP1-00001]  (hidden comment: CAP-NONPOL)
C201  value 6.8p  [AP1-00001]  (hidden comment: CAP-NONPOL)
C202  100n  [AP1-00053]
C203  value 100n  [AP1-00001]  (hidden comment: CAP-NONPOL)
C204  value 100n  [AP1-00001]  (hidden comment: CAP-NONPOL)
C205  value 100n  [AP1-00001]  (hidden comment: CAP-NONPOL)
C206  value 100n  [AP1-00001]  (hidden comment: CAP-NONPOL)
C207  value 100n  [AP1-00001]  (hidden comment: CAP-NONPOL)
C208  value 100n  [AP1-00001]  (hidden comment: CAP-NONPOL)
C209  value 10uF/16V  [AP1-00039]  (hidden comment: CAP-NONPOL)
J200  SMD-STRAP_OPEN  [AP9-00034]  (value not drawn)  (net tie, no BOM)
J201  SMD-STRAP_OPEN  [AP9-00034]  (value not drawn)  (net tie, no BOM)
J202  (no value)  [AP9-00044]  (net tie, no BOM)
J203  MPN: STL21-0730 G TT-10U  [AP8-00257]  (hidden comment: HEADER 2x5)
L200  BLM18PG471SN1  [AP3-00005]
R200  value 39R  [AP2-00011]  (hidden comment: R2)
R201  value 47k  [AP2-00000]  (hidden comment: R2)
R202  value 47k  [AP2-00000]  (hidden comment: R2)
R203  value 30k  [AP2-00000]  (hidden comment: R2)
R204  value 47k  [AP2-00000]  (hidden comment: R2)
R205  value 4.7k  [AP2-00000]  (hidden comment: R2)
R206  value 4.7k  [AP2-00000]  (hidden comment: R2)
R207  value 100k  [AP2-00011]  (hidden comment: R2)
R208  value 39R  [AP2-00011]  (hidden comment: R2)
SW200  value KMS223GPLFG  [AP8-00648]  (hidden comment: Reset switch on PCB Edge)
TP200  TESTPOINT  [AP8-00010]  (value not drawn)  (no BOM)
U200  value SAMD21J18A-AUT  [AP6-00173]  (hidden comment: TQFP64)
XC200  value 32.768kHz +/-20PPM 7pF  SMD  [AP7-00044]  (hidden comment: Farnell order no:1539364)

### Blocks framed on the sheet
I2C PULL-UP: R205 R206
32 kHz Crystal: C200 C201 J202 XC200
RESET button with current limit and noise filter: C202 R207 R208 SW200 TP200
Close to VDDIO/GND pairs: C203-C205
Close to VDDIN: C206
Close to VDDCORE: C208
Close to VDDANA/GNDANA: C207 C209 L200

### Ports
CDC_UART (harness CDC_UART), DGI_SPI (harness DGI_SPI), MCB_AC (harness MCB_AC), MCB_ADC (harness MCB_ADC), MCB_EXTINT (harness MCB_EXTINT), MCB_GPIO (harness MCB_GPIO), MCB_IO (harness MCB_IO), MCB_PWM (harness MCB_PWM), MCB_SPI (harness MCB_SPI), MCB_TWI (harness MCB_TWI), MCB_UART (harness MCB_UART), SWD (harness SWD), TARGET_RESET_SENSE (out), TARGET_USB (harness TARGET_USB), TARGET_VOLTAGE (out)

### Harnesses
SWD: SWDCLK, SWDIO, TARGET_RESET
DGI_SPI: MISO, MOSI, SCK, SS
CDC_UART: RXD, TXD
TARGET_USB: PIN9_MCU_USB_DM, PIN7_MCU_USB_DP
MCB_PWM: PIN28_PWM_UH, PIN29_PWM_UL, PIN30_PWM_VH, PIN31_PWM_VL, PIN32_PWM_WH, PIN33_PWM_WL
MCB_ADC: PIN42_BEMF_UADC, PIN43_BEMF_VADC, PIN44_BEMF_WADC, PIN41_MOTOR_V_ADC, PIN34_ISENSE_COMMON, PIN38_USHUNT_ADC, PIN39_VSHUNT_ADC, PIN40_WSHUNT_ADC
MCB_AC: PIN45_BEMF_UP, PIN46_BEMF_UN, PIN47_BEMF_VP, PIN48_BEMF_VN, PIN49_50_BEMF_W
MCB_SPI: PIN16_FLASH_SCK, PIN17_FLASH_MOSI, PIN15_FLASH_MISO, PIN14_FLASH_SS
MCB_UART: PIN26_UART_RX, PIN27_UART_TX
MCB_TWI: PIN13_TEMP_SCL, PIN12_TEMP_SDA
MCB_EXTINT: PIN51_HALL1, PIN52_HALL2, PIN53_HALL3, PIN55_ENCODER_A, PIN56_ENCODER_B, PIN57_ENCODER_Z
MCB_GPIO: PIN18_GPIO1, PIN19_GPIO2, PIN20_GPIO3, PIN21_GPIO4, PIN22_GPIO5, PIN23_GPIO6, PIN24_GPIO7
MCB_IO: PIN35_ATA_RESET, PIN36_ATA_WD, PIN37_ATA_SLEEP, PIN54_HALL_TRX_OE, PIN25_DRIVER_OCP, PIN58_ENCODER_EN

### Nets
GND: C200.2 C201.2 C202.2 C203.2 C204.2 C205.2 C206.2 C207.2 C208.2 C209.2 J203.3 J203.5 J203.9 R202.1 R204.1 SW200.2 SW200.4 U200.7(GNDANA) U200.22(GND) U200.33(GND) U200.47(GND) U200.54(GND) XC200.3
VCC_MCU_CORE: C208.1 U200.55(VDDCORE)
VCC_MCU_VDDANA: C207.1 C209.1 L200.2 U200.8(VDDANA)
VCC_TARGET_P3V3: C203.1 C204.1 C205.1 C206.1 J203.1 L200.1 R201.2 R205.2 R206.2 R207.2 U200.21(VDDIO) U200.34(VDDIO) U200.48(VDDIO) U200.56(VDDIN)
VCC_TARGET_USB_P5V0: R203.2
EDBG_ADC0: R201.1 R202.2 ; port TARGET_VOLTAGE
EDBG_CDC_USART_RX: J200.2 ; port CDC_UART.TXD
MCU_USB_N: U200.45(USB_DM/PA24) ; port TARGET_USB.PIN9_MCU_USB_DM
MCU_USB_P: U200.46(USB_DP/PA25) ; port TARGET_USB.PIN7_MCU_USB_DP
PA00_XIN32: C200.1 U200.1(PA00) XC200.2
PA01_XOUT32: C201.1 J202.2 U200.2(PA01)
PA02_ADC_AIN0: U200.3(PA02) ; port MCB_ADC.PIN34_ISENSE_COMMON  [project net ISENSE_COMMON]
PA03_EXTINT3: U200.4(PA03) ; port MCB_EXTINT.PIN51_HALL1  [project net HALL1]
PA04_AC_AIN0: U200.13(PA04) ; port MCB_AC.PIN45_BEMF_UP  [project net BEMF_UP]
PA05_AC_AIN1: U200.14(PA05) ; port MCB_AC.PIN46_BEMF_UN  [project net BEMF_UN]
PA06_AC_AIN2: U200.15(PA06) ; port MCB_AC.PIN47_BEMF_VP  [project net BEMF_VP]
PA07_AC_AIN3: U200.16(PA07) ; port MCB_AC.PIN48_BEMF_VN  [project net BEMF_VN]
PA08_TCC0_WO0: U200.17(PA08) ; port MCB_PWM.PIN28_PWM_UH
PA09_TCC0_WO1: U200.18(PA09) ; port MCB_PWM.PIN30_PWM_VH
PA10_TCC0_WO2: U200.19(PA10) ; port MCB_PWM.PIN32_PWM_WH
PA11_ADC_AIN19: U200.20(PA11) ; port MCB_ADC.PIN40_WSHUNT_ADC
PA12_S2_PAD0: U200.29(PA12) ; port MCB_UART.PIN27_UART_TX  [project net EXT1_TXD]
PA13_S2_PAD1: U200.30(PA13) ; port MCB_UART.PIN26_UART_RX  [project net EXT1_RXD]
PA14_TCC0_WO4: U200.31(PA14) ; port MCB_PWM.PIN29_PWM_UL
PA15_TCC0_WO5: U200.32(PA15) ; port MCB_PWM.PIN31_PWM_VL
PA16_TCC0_WO6: U200.35(PA16) ; port MCB_PWM.PIN33_PWM_WL
PA17_IO: U200.36(PA17) ; port MCB_GPIO.PIN23_GPIO6  [project net GPIO6]
PA18_EXTINT2: U200.37(PA18) ; port MCB_EXTINT.PIN52_HALL2  [project net HALL2]
PA19_IO: U200.38(PA19) ; port MCB_GPIO.PIN18_GPIO1  [project net GPIO1]
PA20_S5_PAD2: U200.41(PA20) ; port MCB_SPI.PIN15_FLASH_MISO  [project net FLASH_MISO]
PA21_S5_PAD3: U200.42(PA21) ; port MCB_SPI.PIN14_FLASH_SS  [project net FLASH_SS]
PA22_S3_PAD0: R206.1 U200.43(PA22) ; port MCB_TWI.PIN12_TEMP_SDA
PA23_S3_PAD1: R205.1 U200.44(USB_SOF/PA23) ; port MCB_TWI.PIN13_TEMP_SCL
PA27_USB_VBUS: R203.1 R204.2 U200.51(PA27)
PA28_EXTINT8: U200.53(PA28) ; port MCB_EXTINT.PIN53_HALL3  [project net HALL3]
PA30_SWDCLK: J203.4 U200.57(SWDCLK/PA30) ; port SWD.SWDCLK
PA31_SWDIO: J203.2 U200.58(SWDIO/PA31) ; port SWD.SWDIO
PB00_ADC_AIN8: U200.61(PB00) ; port MCB_ADC.PIN42_BEMF_UADC  [project net BEMF_UADC]
PB01_ADC_AIN9: U200.62(PB01) ; port MCB_ADC.PIN43_BEMF_VADC  [project net BEMF_VADC]
PB02_ADC_AIN10: U200.63(PB02) ; port MCB_ADC.PIN41_MOTOR_V_ADC  [project net MOTOR_VDC]
PB03_IO: U200.64(PB03) ; port MCB_IO.PIN25_DRIVER_OCP  [project net DRIVER_OCP]
PB04_ADC_AIN12: U200.5(PB04) ; port MCB_ADC.PIN38_USHUNT_ADC
PB05_ADC_AIN13: U200.6(PB05) ; port MCB_ADC.PIN39_VSHUNT_ADC
PB06_ADC_AIN14: U200.9(PB06) ; port MCB_ADC.PIN44_BEMF_WADC  [project net BEMF_WADC]
PB07_BEMF_COM_W: U200.10(PB07) ; port MCB_AC.PIN49_50_BEMF_W  [project net BEMF_COM_W]
PB08_IO: U200.11(PB08) ; port MCB_GPIO.PIN19_GPIO2  [project net GPIO2]
PB09_EXTINT09: U200.12(PB09) ; port MCB_EXTINT.PIN55_ENCODER_A  [project net ENCODER_A]
PB10_EXTINT10: U200.23(PB10) ; port MCB_EXTINT.PIN56_ENCODER_B  [project net ENCODER_B]
PB11_IO: U200.24(PB11) ; port MCB_IO.PIN54_HALL_TRX_OE  [project net HALL_TRX_OE]
PB12_S4_PAD0: J200.1 U200.25(PB12) ; port DGI_SPI.MISO
PB13_S4_PAD1: J201.1 U200.26(PB13) ; port DGI_SPI.SS  [project net EDBG_SPI_DGI_SS]
PB14_S4_PAD2: U200.27(PB14) ; port DGI_SPI.MOSI  [project net EDBG_SPI_DGI_MOSI]
PB15_S4_PAD3: U200.28(PB15) ; port DGI_SPI.SCK  [project net EDBG_SPI_DGI_SCK]
PB16_S5_PAD0: U200.39(PB16) ; port MCB_SPI.PIN17_FLASH_MOSI  [project net FLASH_MOSI]
PB17_S5_PAD1: U200.40(PB17) ; port MCB_SPI.PIN16_FLASH_SCK  [project net FLASH_SCK]
PB22_IO: U200.49(PB22) ; port MCB_IO.PIN58_ENCODER_EN  [project net ENCODER_EN]
PB23_EXTINT07: U200.50(PB23) ; port MCB_EXTINT.PIN57_ENCODER_Z  [project net ENCODER_Z]
PB30_IO: U200.59(PB30) ; port MCB_GPIO.PIN24_GPIO7  [project net GPIO7]
PB31_IO: U200.60(PB31) ; port MCB_GPIO.PIN22_GPIO5  [project net GPIO5]
TARGET_RESET: R200.1 ; port SWD.TARGET_RESET
TARGET_RESET_SENSE: C202.1 J203.10 R200.2 R207.1 R208.2 U200.52(~{RESETN}) ; port TARGET_RESET_SENSE
NetJ201_2: J201.2 ; port CDC_UART.RXD
NetJ202_1: J202.1 XC200.1
NetR208_1: R208.1 SW200.1 SW200.5 TP200.1

Not connected (* = marked no-connect by the designer): J203 6* 7* 8*; SW200 3

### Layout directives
differential pair; rule Assembly Testpoint Usage [Testpoint - Not Allowed    Multiple - Not Allowed]: MCU_USB_N, MCU_USB_P
rule Assembly Testpoint Usage [Testpoint - Not Allowed    Multiple - Not Allowed]: NetJ202_1, PA00_XIN32, PA01_XOUT32

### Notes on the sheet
- straps to be in default-open configuration
- Calculation of crystal load capacitors:
  Cext = 2x ( Ccrystal - Cpara - Cpcb )
  Ccrystal = 7.0pF (from crystal datasheet)
  Cpara = 3.15pF (from MCU datasheet)
  Cpcb = 0.5pF (estimate)
  Cext = 2x(7.0pF - 3.15pF - 0.5pF) = 6.7pF
- These straps with SMD pads can be used to place a resistor in the XOUT signal in order to measure the oscillator allowance.
  By default these straps are closed and nothing is mounted on the pads.

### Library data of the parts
C200 C201 = A01-0013: Ceramic capacitor, SMD 0402, NP0, 50V, +/-5%; PartGroup: Capacitors,Ceramic,SMD 0402; TemperatureRange: -55 - +125 deg C
C202-C208 = A01-0246: as C104 on sheet ATSAMD21MOTOR_CONNECTOR
C209 = A01-0491: Ceramic capacitor, SMD 0603, X5R, 16V, 10UF ± 20% (High Density); PartGroup: Capacitors,Ceramic,SMD 0603; Manufacturer: Taiyo Yuden; MPN: EMK107BBJ106MA-T
J200 J201 = A09-0483: as J102 on sheet ATSAMD21MOTOR_CONNECTOR
J202 = A09-0783: Default closed SMD strap, 0603 size; PartGroup: Mechanical devices,PCB implemented components; Value: SMD-STRAP_0603_CLOSED
J203 = A08-0385: 2x5 pin header, 1.27mm pitch, THM; PartGroup: Mechanical devices,Connectors,Pin headers; Manufacturer: Garry; Value: PIN HEADER 2x5
L200 = A03-0035: as L300 on sheet ATSAMD21MOTOR_EDBG
R200 R208 = A02-0178: as R308 on sheet ATSAMD21MOTOR_EDBG
R201 R202 R204 = A02-0252: Thick film resistor, SMD 0402, 1/16W, 1%; PartGroup: Resistors,SMD,0402 1%; TemperatureRange: -55 - +125 deg C
R203 = A02-0247: Thick film resistor, SMD 0402, 1/16W, 1%; PartGroup: Resistors,SMD,0402 1%; TemperatureRange: -55 - +125 deg C
R205 R206 = A02-0228: Thick film resistor, SMD 0402, 1/16W, 1%; PartGroup: Resistors,SMD,0402 1%; TemperatureRange: -55 - +125 deg C
R207 = A02-0260: Thick film resistor, SMD 0402, 1/16W, 1%; PartGroup: Resistors,SMD,0402 1%; TemperatureRange: -55 - +125 deg C
SW200 = A08-1554: KMS Series Microminiature SMT Side Actuated with pegs; PartGroup: Mechanical devices,Switches,SMD; Manufacturer: C&K Components; TemperatureRange: -40°C to 125°C
TP200 = A08-0004: as TP100 on sheet ATSAMD21MOTOR_CONNECTOR
U200 = A06-1041: Atmel 32-bit RISC MCU 64pin; PartGroup: Integrated Circuits,MCU, MPU, DSP,ARM MCU; TemperatureRange: -40°C to +85°C
XC200 = A07-0052: 32k768 crystal, +-20ppm, CL=7pF, max ESR 60kOhm, SMD; PartGroup: Frequency devices,Crystals,SMD; Manufacturer: Micro Crystal; MPN: MS1V-T1K 32.768kHz 7pF +/-20PPM TA; Tolerance: +/- 20 PPM; TemperatureRange: -40 /+85

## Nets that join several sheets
GND: ATSAMD21MOTOR_CONNECTOR (12 pins), ATSAMD21MOTOR_EDBG (27 pins), ATSAMD21MOTOR_TARGET (23 pins)
VCC_EDBG_USB_P5V0: ATSAMD21MOTOR_CONNECTOR (J100.10), ATSAMD21MOTOR_EDBG (U300.A10)
VCC_TARGET_P3V3: ATSAMD21MOTOR_CONNECTOR (10 pins), ATSAMD21MOTOR_EDBG (R311.2), ATSAMD21MOTOR_TARGET (14 pins)
VCC_TARGET_USB_P5V0: ATSAMD21MOTOR_CONNECTOR (J100.8), ATSAMD21MOTOR_TARGET (R203.2)
BEMF_COM_W: ATSAMD21MOTOR_CONNECTOR (R102.2 TP106.1), ATSAMD21MOTOR_TARGET (U200.10)
BEMF_UADC: ATSAMD21MOTOR_CONNECTOR (J100.42), ATSAMD21MOTOR_TARGET (U200.61)
BEMF_UN: ATSAMD21MOTOR_CONNECTOR (J100.46), ATSAMD21MOTOR_TARGET (U200.14)
BEMF_UP: ATSAMD21MOTOR_CONNECTOR (J100.45), ATSAMD21MOTOR_TARGET (U200.13)
BEMF_VADC: ATSAMD21MOTOR_CONNECTOR (J100.43), ATSAMD21MOTOR_TARGET (U200.62)
BEMF_VN: ATSAMD21MOTOR_CONNECTOR (J100.48), ATSAMD21MOTOR_TARGET (U200.16)
BEMF_VP: ATSAMD21MOTOR_CONNECTOR (J100.47), ATSAMD21MOTOR_TARGET (U200.15)
BEMF_WADC: ATSAMD21MOTOR_CONNECTOR (J100.44), ATSAMD21MOTOR_TARGET (U200.9)
DRIVER_OCP: ATSAMD21MOTOR_CONNECTOR (J100.25), ATSAMD21MOTOR_TARGET (U200.64)
EDBG_ADC0: ATSAMD21MOTOR_EDBG (U300.K10), ATSAMD21MOTOR_TARGET (R201.1 R202.2)
EDBG_CDC_USART_RX: ATSAMD21MOTOR_EDBG (U300.F9), ATSAMD21MOTOR_TARGET (J200.2)
EDBG_ID1: ATSAMD21MOTOR_CONNECTOR (J100.6), ATSAMD21MOTOR_EDBG (R300.1 U300.A1)
EDBG_ID2: ATSAMD21MOTOR_CONNECTOR (J100.4), ATSAMD21MOTOR_EDBG (R301.1 U300.B2)
EDBG_SPI_DGI_MOSI: ATSAMD21MOTOR_EDBG (U300.K3), ATSAMD21MOTOR_TARGET (U200.27)
EDBG_SPI_DGI_SCK: ATSAMD21MOTOR_EDBG (U300.J4), ATSAMD21MOTOR_TARGET (U200.28)
EDBG_SPI_DGI_SS: ATSAMD21MOTOR_EDBG (U300.G5), ATSAMD21MOTOR_TARGET (J201.1 U200.26)
EDBG_USB_HS_N: ATSAMD21MOTOR_CONNECTOR (J100.3), ATSAMD21MOTOR_EDBG (R308.1 U300.A9)
EDBG_USB_HS_P: ATSAMD21MOTOR_CONNECTOR (J100.1), ATSAMD21MOTOR_EDBG (R309.1 U300.A8)
ENCODER_A: ATSAMD21MOTOR_CONNECTOR (J100.55 U101.3), ATSAMD21MOTOR_TARGET (U200.12)
ENCODER_B: ATSAMD21MOTOR_CONNECTOR (J100.56 U101.1), ATSAMD21MOTOR_TARGET (U200.23)
ENCODER_EN: ATSAMD21MOTOR_CONNECTOR (J100.58), ATSAMD21MOTOR_TARGET (U200.49)
ENCODER_Z: ATSAMD21MOTOR_CONNECTOR (J100.57), ATSAMD21MOTOR_TARGET (U200.50)
EXT1_RXD: ATSAMD21MOTOR_CONNECTOR (J100.26), ATSAMD21MOTOR_TARGET (U200.30)
EXT1_TXD: ATSAMD21MOTOR_CONNECTOR (J100.27), ATSAMD21MOTOR_TARGET (U200.29)
FLASH_MISO: ATSAMD21MOTOR_CONNECTOR (J100.15), ATSAMD21MOTOR_TARGET (U200.41)
FLASH_MOSI: ATSAMD21MOTOR_CONNECTOR (J100.17), ATSAMD21MOTOR_TARGET (U200.39)
FLASH_SCK: ATSAMD21MOTOR_CONNECTOR (J100.16), ATSAMD21MOTOR_TARGET (U200.40)
FLASH_SS: ATSAMD21MOTOR_CONNECTOR (J100.14), ATSAMD21MOTOR_TARGET (U200.42)
GPIO1: ATSAMD21MOTOR_CONNECTOR (J102.1 U101.4), ATSAMD21MOTOR_TARGET (U200.38)
GPIO2: ATSAMD21MOTOR_CONNECTOR (J100.19), ATSAMD21MOTOR_TARGET (U200.11)
GPIO5: ATSAMD21MOTOR_CONNECTOR (J100.22), ATSAMD21MOTOR_TARGET (U200.60)
GPIO6: ATSAMD21MOTOR_CONNECTOR (J100.23), ATSAMD21MOTOR_TARGET (U200.36)
GPIO7: ATSAMD21MOTOR_CONNECTOR (J100.24), ATSAMD21MOTOR_TARGET (U200.59)
HALL1: ATSAMD21MOTOR_CONNECTOR (J100.51), ATSAMD21MOTOR_TARGET (U200.4)
HALL2: ATSAMD21MOTOR_CONNECTOR (J100.52), ATSAMD21MOTOR_TARGET (U200.37)
HALL3: ATSAMD21MOTOR_CONNECTOR (J100.53), ATSAMD21MOTOR_TARGET (U200.53)
HALL_TRX_OE: ATSAMD21MOTOR_CONNECTOR (J100.54), ATSAMD21MOTOR_TARGET (U200.24)
ISENSE_COMMON: ATSAMD21MOTOR_CONNECTOR (J100.34), ATSAMD21MOTOR_TARGET (U200.3)
MCU_USB_N: ATSAMD21MOTOR_CONNECTOR (J100.9), ATSAMD21MOTOR_TARGET (U200.45)
MCU_USB_P: ATSAMD21MOTOR_CONNECTOR (J100.7), ATSAMD21MOTOR_TARGET (U200.46)
MOTOR_VDC: ATSAMD21MOTOR_CONNECTOR (J100.41), ATSAMD21MOTOR_TARGET (U200.63)
NetJ201_2: ATSAMD21MOTOR_EDBG (R306.1), ATSAMD21MOTOR_TARGET (J201.2)
PA08_TCC0_WO0: ATSAMD21MOTOR_CONNECTOR (J100.28 TP100.1), ATSAMD21MOTOR_TARGET (U200.17)
PA09_TCC0_WO1: ATSAMD21MOTOR_CONNECTOR (J100.30 TP102.1), ATSAMD21MOTOR_TARGET (U200.18)
PA10_TCC0_WO2: ATSAMD21MOTOR_CONNECTOR (J100.32 TP104.1), ATSAMD21MOTOR_TARGET (U200.19)
PA11_ADC_AIN19: ATSAMD21MOTOR_CONNECTOR (J100.40), ATSAMD21MOTOR_TARGET (U200.20)
PA14_TCC0_WO4: ATSAMD21MOTOR_CONNECTOR (J100.29 TP101.1), ATSAMD21MOTOR_TARGET (U200.31)
PA15_TCC0_WO5: ATSAMD21MOTOR_CONNECTOR (J100.31 TP103.1), ATSAMD21MOTOR_TARGET (U200.32)
PA16_TCC0_WO6: ATSAMD21MOTOR_CONNECTOR (J100.33 TP105.1), ATSAMD21MOTOR_TARGET (U200.35)
PA22_S3_PAD0: ATSAMD21MOTOR_CONNECTOR (J100.12), ATSAMD21MOTOR_TARGET (R206.1 U200.43)
PA23_S3_PAD1: ATSAMD21MOTOR_CONNECTOR (J100.13), ATSAMD21MOTOR_TARGET (R205.1 U200.44)
PA30_SWDCLK: ATSAMD21MOTOR_EDBG (U300.D6), ATSAMD21MOTOR_TARGET (J203.4 U200.57)
PA31_SWDIO: ATSAMD21MOTOR_EDBG (U300.C5), ATSAMD21MOTOR_TARGET (J203.2 U200.58)
PB04_ADC_AIN12: ATSAMD21MOTOR_CONNECTOR (J100.38), ATSAMD21MOTOR_TARGET (U200.5)
PB05_ADC_AIN13: ATSAMD21MOTOR_CONNECTOR (J100.39), ATSAMD21MOTOR_TARGET (U200.6)
PB12_S4_PAD0: ATSAMD21MOTOR_EDBG (R307.2), ATSAMD21MOTOR_TARGET (J200.1 U200.25)
TARGET_RESET: ATSAMD21MOTOR_EDBG (U300.B4), ATSAMD21MOTOR_TARGET (R200.1)
TARGET_RESET_SENSE: ATSAMD21MOTOR_EDBG (U300.H2), ATSAMD21MOTOR_TARGET (6 pins)

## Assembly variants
Default_assembly: not fitted C300 R301
Production variant: not fitted J100 J203 R101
